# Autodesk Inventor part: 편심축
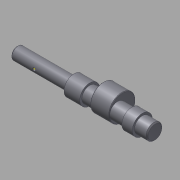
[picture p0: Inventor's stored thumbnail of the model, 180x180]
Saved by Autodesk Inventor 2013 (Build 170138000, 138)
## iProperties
Company: 한국ATC센터
Created: 2015-12
Part Number: 편심축
Document SubType Name: Modeling
Designer: mdu
Density: 7.86 g/cm^3
Mass: 248.518 g
Surface Area: 94.9962 cm^2
Volume: 31.6181 cm^3
Material: 강철, 연강
Author: mdu
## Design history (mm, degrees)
sketch "스케치1"
  geometry: L1 (-84.5, 0)-(84.5, 0); L2 (-84.5, 0)-(-84.5, 6); L3 (-84.5, 6)-(-30.5, 6); L4 (-30.5, 6)-(-30.5, 9.5); L5 (-30.5, 9.5)-(-15.5, 9.5); L6 (-15.5, 9.5)-(-15.5, 7.5); L7 (-15.5, 7.5)-(46.5, 7.5); L8 (84.5, 6)-(84.5, 0); L9 (34.5, 7.5)-(34.5, 9.5); L10 (34.5, 9.5)-(24.5, 9.5); L11 (24.5, 9.5)-(24.5, 7.5); L12 (46.5, 7.5)-(46.5, 6); L13 (46.5, 6)-(84.5, 6); 2 further points
  constraints: 26 end point, 6 parallel, 6 perpendicular, 2 point on line, 1 coincident, 1 horizontal, 1 midpoint
  dimensions: "d1" = 12 diameter of L3 L1; "d2" = 15 diameter of L7 L1; "d4" = 15 distance of L4.end L5.end; "d5" = 19 diameter of L5 L1; "d24" = 10 distance of L9.end L10.end; "d25" = 19 diameter of L10 L1; "d27" = 40 distance between parallel lines of L11 L6; "d28" = 54 distance of L2.end L3.end; "d29" = 50 distance between parallel lines of L8 L9; "d41" = 38 distance between parallel lines of L8 L12; "d42" = 12 diameter of L13 L1
revolve "회전1" stored, may be unused: angle "d6" = 90 deg
node "작업 평면1"
sketch "스케치2"
  geometry: C1 r 7.5 at (0, 0) reference; C2 r 12.5 at (0, 4.5); 1 further point
  constraints: 1 centre point, 1 vertical alignment
  dimensions: "d8" = 4.5 distance of point (0, 0) C2.centre; "d9" = 25 diameter of C2
extrude "돌출1" join sketch "스케치2" distance "d10" = 18; taper "d11" = 0 deg
chamfer "모따기1" distance "d12" = 1; stored, may be unused: second distance "d13" = 2, angle "d14" = 45 deg
chamfer "모따기2" distance "d15" = 0.5; stored, may be unused: second distance "d16" = 2, angle "d17" = 45 deg
node "작업 평면2"
sketch "스케치3"
  geometry: L1 (4, -2)-(18, -2); L2 (18, 2)-(4, 2); L3 (27, 5)-(27, -5) reference; A1 r 2 centre (18, 0) between (18, -2) and (18, 2); A2 r 2 centre (4, 0) between (4, 2) and (4, -2); 2 further points
  constraints: 4 end point, 4 point on circle, 4 tangent, 2 centre point, 1 horizontal, 1 horizontal alignment, 1 midpoint, 1 parallel
  dimensions: "d18" = 7 distance edge to line of A1 L3; "d19" = 4 distance between parallel lines of L2 L1; "d20" = 18 dimension on A1 A2
extrude "돌출2" cut sketch "스케치3" distance "d21" = 2.5; taper "d22" = 0 deg
revolve "회전2" stored, may be unused: angle "d26" = 90 deg
node "작업 평면3"
sketch "스케치4"
  geometry: L1 (44, 5)-(44, -5) reference; 2 further points
  constraints: 1 horizontal alignment
  dimensions: "d30" = 12 distance from line of point (32, 0) L1
hole "구멍1" sketch "스케치4" at (32, 0) diameter "d31" = 6; stored, may be unused: countersink angle "d35" = 90 deg, drill point angle "d37" = 118 deg; dims "d32" = 6, "d33" = 14, "d34" = 3, "d36" = 8
node "작업 평면4"
sketch "스케치5"
  geometry: C1 r 3 at (32, 0) reference; C2 r 8 at (32, 0); 2 further points
  constraints: 1 centre point, 1 coincident, 1 other
  dimensions: "d38" = 16 diameter of C2
extrude "돌출3" cut sketch "스케치5" distance "d39" = 3; taper "d40" = 0 deg
sketch "스케치6"
  geometry: L1 (-83.5, -6)-(-30.5, -6) reference; L2 (-84.5, -5)-(-84.5, 5) reference; L3 (-83.5, 6)-(-30.5, 6) reference; L4 (-62.5, 6)-(-62.5, -6); L5 (-62.5, -6)-(-61, -6); L6 (-62.5, -4.5)-(-61, -6); L7 (-62.5, -6)-(-62.5, -4.5); 2 further points
  constraints: 8 end point, 4 point on line, 2 perpendicular, 1 coincident
  dimensions: "d43" = 22 distance between parallel lines of L4 L2; "d44" = 45 deg angle of L6 L7; "d45" = 3 diameter of L5.end L4
revolve "회전3" stored, may be unused: angle "d46" = 90 deg
node "작업점1"
chamfer "모따기3" distance "d47" = 0.5; stored, may be unused: second distance "d48" = 2, angle "d49" = 45 deg
sketch "스케치7"
  geometry: C1 r 7.5 at (0, 0) reference; 1 further point
extrude "돌출4" cut sketch "스케치7" stored distance "d50" = 10; taper "d51" = 0 deg
chamfer "모따기4" distance "d52" = 1; stored, may be unused: second distance "d53" = 2, angle "d54" = 45 deg
node "작업 평면5"
node "솔리드1"
node "투영된 루프1"
other parameters: "d7" = 8.5
